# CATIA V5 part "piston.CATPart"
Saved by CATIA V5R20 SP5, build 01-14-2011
Part number: piston
Bounding box of the stored display mesh (mm): x -10 to 20, y 188.114 to 248.114, z -12.5 to 12.5
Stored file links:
  F:\projet\yyang_IAO\piston.CATPart
  F:\projet\yyang_IAO\iao.CATProduct
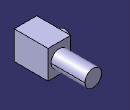
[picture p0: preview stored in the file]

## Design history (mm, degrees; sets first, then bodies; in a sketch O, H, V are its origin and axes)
External parameters (linked from other documents)
  `External.rayon de liaison` = 5 mm
  External.epaisseur = 10 mm
Set1
  Plane1: linked copy from another document
  Point1: linked copy from another document
Body1 (main body)
  Sketch1 on Plane1, origin (0, 0, 0), H (0, 1, 0), V (0, 0, 1)
    line L1 (188.1141, 12.5) -> (218.1141, 12.5)
    line L2 (218.1141, 12.5) -> (218.1141, -12.5)
    line L3 (218.1141, -12.5) -> (188.1141, -12.5)
    line L4 (188.1141, -12.5) -> (188.1141, 12.5)
    reference projected point E1 (203.1141, 0) from Point1
    reference projected point E2 (203.1141, 0) from Point1
    length L2 = 25
    length L3 = 30
    distance L3 E1 = 12.5
    distance L2 E2 = 15
    horizontal: L1 H, L3 H
    vertical: L2 V, L4 V
  Pad1: profile Sketch1, direction (1, 0, 0), length 20
  Sketch2 on start face of Pad1, origin (0, 0, 0), H (0, -1, 0), V (0, 0, 1)
    circle A1 centre (-203.1141, 0) radius 5
    point P1 (-203.1141, 0)
    reference projected point E1 (-203.1141, 0) from Point1
    reference projected point E2 (-203.1141, 0) from Point1
    distance A1 E2 = 5 {= `External.rayon de liaison`}
    coincidence: P1 E1
  Pad2: profile Sketch2, direction (-1, 0, 0), length 10 {= External.epaisseur}
  Sketch3 on face of Pad1 from Sketch1.L2, origin (0, 218.1141, 0), H (-1, 0, 0), V (0, 0, 1)
    circle A1 centre (-10, 0) radius 7.5
    point P1 (-10, 0)
    reference projected line E1 (0, 12.5) -> (-20, 12.5) from edge [face of Pad1 from Sketch1.L1 | face of Pad1 from Sketch1.L2]
    reference projected line E2 (-20, -12.5) -> (-20, 12.5) from edge [face of Pad1 from Sketch1.L2 | end face of Pad1]
    distance P1 E1 = 12.5
    distance P1 E2 = 10
    radius A1 = 7.5
  Pad3: profile Sketch3, direction (0, 1, 0), length 30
